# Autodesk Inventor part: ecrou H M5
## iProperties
Author: chr
Created: 2001-05
Part Number: ecrou H M5
Material: Par défaut
Document SubType Name: Modélisation
Designer: chr
Control State: 0
Master: False
Checked Out: False
PropertySet Name: Design Tracking Control
Shininess: 20.0
PropertySet Name: _Private Model Information
Length Units: 11269
Angle Units: 11283
Time Units: 11279
Mass Units: 11290
Length Display Precision: 3
Angle Display Precision: 2
Compacted: False
Density: 0.0
Volumn: 0.0
Area: 0.0
PropertySet Name: Model Information
